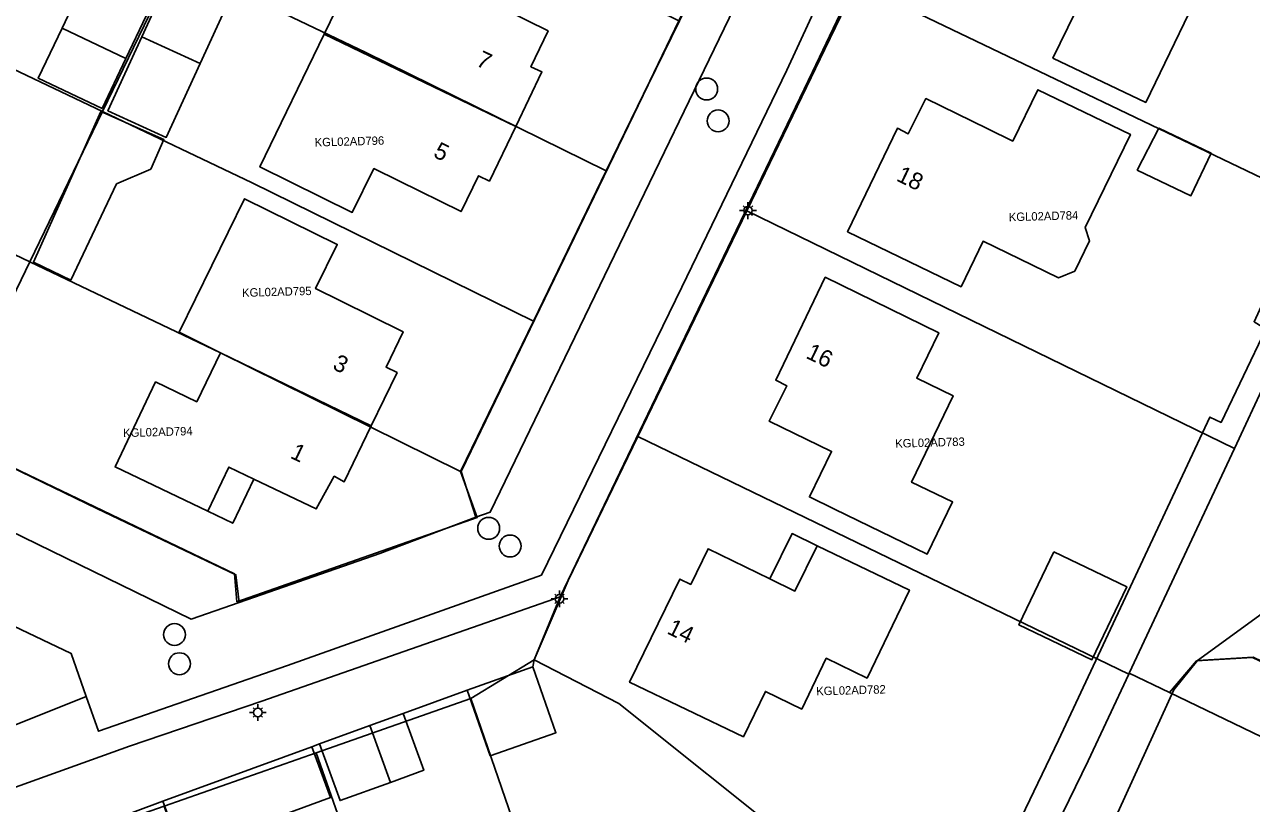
# Model space of a CAD drawing. Extents: x 124901 to 125496, y 515369 to 515789.
# Drawn here: x 125375.1 to 125447.9, y 515642.6 to 515688.8 of the extents above; entities that cross this region are included whole.
import ezdxf

# ---------------------------------------------------------------- set-up
doc = ezdxf.new("R2010")
doc.units = 0
for name, color, linetype in [('Gebouw', 7, 'Continuous'), ('Lichtmast', 7, 'Continuous'), ('Luifel', 7, 'Continuous'), ('Onbegroeid terrein', 7, 'Continuous'), ('Parkeren', 7, 'Continuous'), ('Perceelnummers', 7, 'Continuous'), ('Perceelsgrenzen', 7, 'Continuous'), ('Putten', 7, 'Continuous'), ('Scheiding', 7, 'Continuous'), ('Teksten', 7, 'Continuous'), ('Vegetatie', 7, 'Continuous'), ('Voetpad', 7, 'Continuous'), ('Water', 7, 'Continuous'), ('Wegen lokale weg', 7, 'Continuous')]:
    doc.layers.add(name, color=color, linetype=linetype)

msp = doc.modelspace()

# ---------------------------------------------------------------- linework, layer by layer
at = {"layer": 'Gebouw'}
for points in [[(125433.312, 515694.13), (125432.28, 515692), (125435.972, 515690.217), (125437.458, 515689.5), (125436.149, 515686.79), (125441.65, 515684.17), (125445.627, 515692.406), (125441.046, 515694.619), (125442.35, 515697.32), (125435.61, 515700.54), (125432.65, 515694.45)], [(125405.175, 515686.283), (125406.19, 515688.41), (125402.491, 515690.233), (125401.011, 515690.963), (125402.299, 515693.575), (125396.814, 515696.279), (125392.911, 515688.22), (125404.274, 515682.742), (125405.83, 515685.97)], [(125381.148, 515686.776), (125377.355, 515688.574), (125375.945, 515685.598), (125379.738, 515683.8)], [(125402.712, 515679.503), (125404.274, 515682.742), (125392.911, 515688.22), (125389.097, 515680.344), (125394.572, 515677.638), (125395.861, 515680.245), (125397.34, 515679.514), (125401.03, 515677.69), (125402.056, 515679.819)], [(125380.081, 515683.67), (125383.542, 515682.087), (125385.548, 515686.474), (125382.086, 515688.057)], [(125423.96, 515676.5), (125430.7, 515673.238), (125432.007, 515675.938), (125434.167, 515674.892), (125436.485, 515673.77), (125437.445, 515674.165), (125438.313, 515675.96), (125438.06, 515676.74), (125440.74, 515682.27), (125435.25, 515684.92), (125433.766, 515681.876), (125432.283, 515682.599), (125428.61, 515684.39), (125427.564, 515682.307), (125426.92, 515682.63)], [(125393.684, 515675.747), (125388.182, 515678.455), (125384.313, 515670.544), (125386.751, 515669.309), (125395.701, 515664.985), (125397.23, 515668.15), (125396.58, 515668.461), (125397.59, 515670.57), (125393.875, 515672.398), (125392.395, 515673.127)], [(125428.07, 515667.805), (125429.37, 515670.51), (125422.64, 515673.8), (125419.7, 515667.69), (125420.355, 515667.368), (125419.32, 515665.26), (125423.012, 515663.468), (125421.7, 515660.768), (125423.184, 515660.047), (125428.684, 515657.376), (125430.19, 515660.48), (125427.764, 515661.646), (125430.226, 515666.768)], [(125392.44, 515660.06), (125393.503, 515661.997), (125394.1, 515661.67), (125395.701, 515664.985), (125386.751, 515669.309), (125385.349, 515666.414), (125382.907, 515667.596), (125380.5, 515662.55), (125385.996, 515659.928), (125387.25, 515662.546), (125388.738, 515661.833)], [(125419.09, 515649.238), (125421.24, 515648.19), (125422.699, 515651.203), (125425.12, 515650.03), (125427.628, 515655.247), (125422.15, 515657.88), (125420.841, 515655.189), (125419.357, 515655.911), (125415.684, 515657.698), (125414.655, 515655.582), (125414, 515655.9), (125411.03, 515649.78), (125417.78, 515646.55)], [(125392.627, 515646.124), (125393.848, 515642.761), (125396.839, 515643.846), (125395.619, 515647.21)]]:
    msp.add_lwpolyline(points, close=True, dxfattribs=at)
at = {"layer": 'Lichtmast'}
for p, q in [((125417.837, 515677.963), (125417.767, 515678.034)), ((125418.049, 515678.051), (125418.049, 515678.251)), ((125418.261, 515677.963), (125418.332, 515678.035)), ((125417.749, 515677.752), (125417.549, 515677.751)), ((125417.837, 515677.539), (125417.765, 515677.468)), ((125418.049, 515677.451), (125418.049, 515677.251)), ((125418.261, 515677.539), (125418.331, 515677.468)), ((125418.349, 515677.751), (125418.549, 515677.751)), ((125406.57, 515654.73), (125406.37, 515654.729)), ((125406.658, 515654.941), (125406.588, 515655.012)), ((125406.87, 515655.029), (125406.87, 515655.229)), ((125407.082, 515654.941), (125407.153, 515655.013)), ((125407.17, 515654.729), (125407.37, 515654.729)), ((125406.658, 515654.517), (125406.586, 515654.446)), ((125406.87, 515654.429), (125406.87, 515654.229)), ((125407.082, 515654.517), (125407.152, 515654.446)), ((125388.759, 515648.201), (125388.689, 515648.272)), ((125388.971, 515648.289), (125388.971, 515648.489)), ((125389.183, 515648.201), (125389.254, 515648.273)), ((125388.671, 515647.99), (125388.471, 515647.989)), ((125388.759, 515647.777), (125388.687, 515647.706)), ((125388.971, 515647.689), (125388.971, 515647.489)), ((125389.183, 515647.777), (125389.253, 515647.706)), ((125389.271, 515647.989), (125389.471, 515647.989))]:
    msp.add_line(p, q, dxfattribs=at)
for centre in [(125418.049, 515677.751), (125406.87, 515654.729), (125388.971, 515647.989)]:
    msp.add_circle(centre, 0.25, dxfattribs=at)
at = {"layer": 'Luifel'}
for points in [[(125382.086, 515688.057), (125385.548, 515686.474), (125387.563, 515690.88), (125384.101, 515692.462)], [(125381.148, 515686.776), (125382.347, 515689.306), (125378.554, 515691.104), (125377.355, 515688.574)], [(125380.581, 515679.332), (125382.615, 515680.203), (125383.401, 515681.963), (125379.663, 515683.632), (125375.665, 515674.683), (125377.869, 515673.634)], [(125442.422, 515682.631), (125441.152, 515680.149), (125444.338, 515678.632), (125445.536, 515681.147)], [(125388.738, 515661.833), (125387.25, 515662.546), (125385.996, 515659.928), (125387.484, 515659.215)], [(125420.841, 515655.189), (125422.15, 515657.88), (125420.666, 515658.602), (125419.357, 515655.911)], [(125436.2, 515657.509), (125434.132, 515653.185), (125438.456, 515651.117), (125440.524, 515655.441)], [(125401.387, 515649.315), (125402.76, 515645.414), (125406.661, 515646.787), (125405.288, 515650.687)], [(125397.596, 515647.927), (125395.619, 515647.21), (125396.839, 515643.846), (125398.817, 515644.564)], [(125392.17, 515645.96), (125383.332, 515642.723), (125384.436, 515639.707), (125393.275, 515642.944)]]:
    msp.add_lwpolyline(points, close=True, dxfattribs=at)
at = {"layer": 'Onbegroeid terrein'}
for points in [[(125387.675, 515656.161), (125387.857, 515654.507), (125396.207, 515657.408), (125401.906, 515659.565), (125401.03, 515662.274), (125412.127, 515685.205), (125422.352, 515706.097), (125424.481, 515710.447), (125424.391, 515710.491), (125423.853, 515710.375), (125408.558, 515717.624), (125373.683, 515734.37), (125372.5, 515731.951), (125364.983, 515716.105), (125345.743, 515676.245), (125361.449, 515668.777), (125379.413, 515660.079)], [(125432.28, 515692), (125433.312, 515694.13), (125432.65, 515694.45), (125435.61, 515700.54), (125442.35, 515697.32), (125441.046, 515694.619), (125445.627, 515692.406), (125441.65, 515684.17), (125436.149, 515686.79), (125437.458, 515689.5), (125435.972, 515690.217)], [(125404.274, 515682.742), (125402.712, 515679.503), (125402.056, 515679.819), (125401.03, 515677.69), (125397.34, 515679.514), (125395.861, 515680.245), (125394.572, 515677.638), (125389.097, 515680.344), (125392.911, 515688.22), (125396.814, 515696.279), (125402.299, 515693.575), (125401.011, 515690.963), (125402.491, 515690.233), (125406.19, 515688.41), (125405.175, 515686.283), (125405.83, 515685.97)], [(125377.355, 515688.574), (125381.148, 515686.776), (125379.738, 515683.8), (125375.945, 515685.598)], [(125385.548, 515686.474), (125383.542, 515682.087), (125380.081, 515683.67), (125382.086, 515688.057)], [(125430.7, 515673.238), (125423.96, 515676.5), (125426.92, 515682.63), (125427.564, 515682.307), (125428.61, 515684.39), (125432.283, 515682.599), (125433.766, 515681.876), (125435.25, 515684.92), (125440.74, 515682.27), (125438.06, 515676.74), (125438.313, 515675.96), (125437.445, 515674.165), (125436.485, 515673.77), (125434.167, 515674.892), (125432.007, 515675.938)], [(125393.503, 515661.997), (125392.44, 515660.06), (125388.738, 515661.833), (125387.25, 515662.546), (125385.996, 515659.928), (125380.5, 515662.55), (125382.907, 515667.596), (125385.349, 515666.414), (125386.751, 515669.309), (125384.313, 515670.544), (125388.182, 515678.455), (125393.684, 515675.747), (125392.395, 515673.127), (125393.875, 515672.398), (125397.59, 515670.57), (125396.58, 515668.461), (125397.23, 515668.15), (125395.701, 515664.985), (125394.1, 515661.67)], [(125429.37, 515670.51), (125428.07, 515667.805), (125430.226, 515666.768), (125427.764, 515661.646), (125430.19, 515660.48), (125428.684, 515657.376), (125423.184, 515660.047), (125421.7, 515660.768), (125423.012, 515663.468), (125419.32, 515665.26), (125420.355, 515667.368), (125419.7, 515667.69), (125422.64, 515673.8)], [(125421.24, 515648.19), (125419.09, 515649.238), (125417.78, 515646.55), (125411.03, 515649.78), (125414, 515655.9), (125414.655, 515655.582), (125415.684, 515657.698), (125419.357, 515655.911), (125420.841, 515655.189), (125422.15, 515657.88), (125427.628, 515655.247), (125425.12, 515650.03), (125422.699, 515651.203)]]:
    msp.add_lwpolyline(points, close=True, dxfattribs=at)
for points in [[(125429.798, 515702.583), (125421.887, 515685.97), (125412.818, 515667.163), (125406.911, 515654.851), (125405.36, 515651.11), (125405.288, 515650.687), (125401.387, 515649.315), (125397.596, 515647.927), (125395.619, 515647.21), (125396.839, 515643.846), (125393.848, 515642.761), (125392.627, 515646.124), (125392.17, 515645.96), (125383.332, 515642.723), (125378.729, 515641.005), (125374.409, 515639.418)], [(125490.925, 515630.677), (125448.027, 515651.268), (125444.728, 515651.073), (125443.321, 515649.329), (125433.556, 515627.939), (125431.85, 515627.386), (125429.766, 515628.208), (125428.663, 515630.094), (125436.481, 515646.34), (125445.451, 515665.509), (125446.119, 515665.186), (125448.787, 515670.727), (125448.083, 515671.163), (125452.441, 515680.669), (125457.131, 515690.833)]]:
    msp.add_lwpolyline(points, dxfattribs=at)
at = {"layer": 'Parkeren'}
msp.add_lwpolyline([(125424.616, 515705.029), (125422.352, 515706.097), (125412.127, 515685.205), (125401.03, 515662.274), (125401.906, 515659.565), (125402.757, 515659.867)], close=True, dxfattribs=at)
at = {"layer": 'Perceelsgrenzen'}
for points in [[(125345.632, 515676.323), (125350.605, 515686.696), (125354.889, 515695.633), (125359.171, 515704.565), (125363.512, 515713.469), (125367.85, 515722.367), (125374.626, 515736.264), (125398.05, 515725.06), (125399.454, 515724.383), (125423.37, 515712.85), (125423.634, 515712.729), (125425.072, 515712.068), (125418.239, 515697.902), (125413.944, 515688.996), (125412.226, 515685.435), (125409.64, 515680.099), (125405.324, 515671.192), (125401, 515662.27), (125401.99, 515659.56), (125387.73, 515654.56), (125387.592, 515656.202), (125370.466, 515664.415)], [(125453.316, 515677.409), (125424.5, 515691.221), (125432.811, 515708.356), (125432.874, 515708.485), (125461.248, 515694.727)], [(125354.889, 515695.633), (125359.171, 515704.565), (125372.598, 515698.005), (125384.059, 515692.535), (125379.751, 515683.623), (125370.719, 515687.915)], [(125409.64, 515680.099), (125395.383, 515687.131), (125384.059, 515692.535), (125388.371, 515701.456), (125397.272, 515697.224), (125413.944, 515688.996), (125412.226, 515685.435)], [(125350.605, 515686.696), (125354.889, 515695.633), (125370.719, 515687.915), (125379.751, 515683.623), (125375.444, 515674.713), (125363.983, 515680.184)], [(125405.324, 515671.192), (125388.639, 515679.4), (125379.751, 515683.623), (125384.059, 515692.535), (125395.383, 515687.131), (125409.64, 515680.099)], [(125417.983, 515677.745), (125422.606, 515687.317), (125424.5, 515691.221), (125453.316, 515677.409), (125452.553, 515675.743), (125446.912, 515663.647)], [(125350.605, 515686.696), (125363.983, 515680.184), (125375.444, 515674.713), (125370.466, 515664.415), (125345.632, 515676.323)], [(125401, 515662.27), (125386.754, 515669.315), (125375.444, 515674.713), (125379.751, 515683.623), (125388.639, 515679.4), (125405.324, 515671.192)], [(125440.672, 515650.329), (125440.645, 515650.271), (125411.516, 515664.357), (125417.983, 515677.745), (125446.912, 515663.647)], [(125370.466, 515664.415), (125375.444, 515674.713), (125386.754, 515669.315), (125401, 515662.27), (125401.99, 515659.56), (125387.73, 515654.56), (125387.592, 515656.202)], [(125405.36, 515651.11), (125407.38, 515655.81), (125411.516, 515664.357), (125440.645, 515650.271), (125438.238, 515645.132), (125432.962, 515634.284), (125420.94, 515640.11), (125410.39, 515648.52)], [(125410.753, 515622.315), (125401.6, 515648.81), (125405.36, 515651.11), (125410.39, 515648.52), (125420.94, 515640.11), (125432.962, 515634.284), (125430.488, 515629.198)], [(125443.053, 515649.181), (125444.658, 515651.051), (125447.978, 515651.259), (125460.02, 515645.53), (125463.963, 515643.642), (125462.19, 515639.955)], [(125458.523, 515632.331), (125454.483, 515623.931), (125454.428, 515623.816), (125453.982, 515624.032), (125448.8, 515613.204), (125432.377, 515621.151), (125427.879, 515623.328), (125430.488, 515629.198), (125432.962, 515634.284), (125438.238, 515645.132), (125440.645, 515650.271), (125440.672, 515650.329), (125443.053, 515649.181), (125462.19, 515639.955), (125462.144, 515639.859), (125461.924, 515639.69), (125461.215, 515638.361), (125459.902, 515635.812), (125458.642, 515633.35)], [(125401.726, 515619.167), (125392.439, 515645.595), (125401.6, 515648.81), (125410.753, 515622.315)], [(125392.524, 515615.957), (125383.42, 515642.43), (125392.439, 515645.595), (125401.726, 515619.167)]]:
    msp.add_lwpolyline(points, close=True, dxfattribs=at)
for points in [[(125461.248, 515694.727), (125453.316, 515677.409), (125452.553, 515675.743), (125446.912, 515663.647), (125440.672, 515650.329), (125443.053, 515649.181), (125444.658, 515651.051), (125447.978, 515651.259), (125460.02, 515645.53), (125463.963, 515643.642), (125481.177, 515635.398), (125481.222, 515635.377), (125481.552, 515635.219), (125490.925, 515630.741)], [(125374.35, 515639.28), (125383.42, 515642.43), (125392.439, 515645.595), (125401.6, 515648.81), (125405.36, 515651.11), (125407.38, 515655.81), (125411.516, 515664.357), (125417.983, 515677.745), (125422.606, 515687.317), (125424.5, 515691.221)]]:
    msp.add_lwpolyline(points, dxfattribs=at)
at = {"layer": 'Putten'}
for centre in [(125415.6, 515684.96), (125416.28, 515683.07), (125402.67, 515658.91), (125403.94, 515657.86), (125384.03, 515652.61), (125384.32, 515650.88)]:
    msp.add_circle(centre, 0.65, dxfattribs=at)
at = {"layer": 'Scheiding'}
msp.add_lwpolyline([(125361.449, 515668.777), (125379.413, 515660.079)], dxfattribs=at)
at = {"layer": 'Vegetatie'}
for points in [[(125387.857, 515654.507), (125387.675, 515656.161), (125379.413, 515660.079), (125361.449, 515668.777), (125345.743, 515676.245), (125344.287, 515673.229), (125344.617, 515672.981), (125344.963, 515672.755), (125345.959, 515672.271), (125361.779, 515664.844), (125385.018, 515653.521)], [(125368.071, 515656.163), (125365.82, 515651.552), (125374.603, 515647.262), (125378.796, 515648.945), (125377.898, 515651.479), (125370.197, 515655.148)]]:
    msp.add_lwpolyline(points, close=True, dxfattribs=at)
msp.add_lwpolyline([(125374.409, 515639.418), (125378.729, 515641.005), (125383.332, 515642.723), (125392.17, 515645.96), (125392.627, 515646.124), (125395.619, 515647.21), (125397.596, 515647.927), (125401.387, 515649.315), (125405.288, 515650.687), (125405.36, 515651.11), (125406.911, 515654.851), (125389.202, 515648.653), (125381.355, 515645.99), (125372.6, 515642.854)], dxfattribs=at)
at = {"layer": 'Voetpad'}
msp.add_lwpolyline([(125372.6, 515642.854), (125381.355, 515645.99), (125389.202, 515648.653), (125406.911, 515654.851), (125412.818, 515667.163), (125421.887, 515685.97), (125429.798, 515702.583), (125430.732, 515704.484), (125430.629, 515704.536), (125429.368, 515705.152), (125429.265, 515705.202), (125428.315, 515703.282), (125420.361, 515686.071), (125414.125, 515673.202), (125405.801, 515656.14), (125390.738, 515650.782), (125379.528, 515646.88), (125378.796, 515648.945), (125374.603, 515647.262)], dxfattribs=at)
at = {"layer": 'Water'}
for points in [[(125457.131, 515690.833), (125452.441, 515680.669), (125448.083, 515671.163), (125448.787, 515670.727), (125446.119, 515665.186), (125445.451, 515665.509), (125436.481, 515646.34), (125428.663, 515630.094), (125429.766, 515628.208), (125431.85, 515627.386), (125433.556, 515627.939), (125443.321, 515649.329), (125444.728, 515651.073), (125454.573, 515658.231), (125461.167, 515672.009), (125466.419, 515682.908), (125469.241, 515688.71), (125472.559, 515695.531)], [(125484.458, 515640.311), (125479.957, 515642.488), (125478.294, 515643.292), (125478.266, 515643.281), (125477.672, 515643.566), (125456.22, 515653.859), (125454.714, 515655.957), (125454.573, 515658.231), (125444.728, 515651.073), (125448.027, 515651.268), (125490.925, 515630.677)]]:
    msp.add_lwpolyline(points, dxfattribs=at)
at = {"layer": 'Wegen lokale weg'}
for points in [[(125425.14, 515704.782), (125424.616, 515705.029), (125402.757, 515659.867), (125401.906, 515659.565), (125396.207, 515657.408), (125387.857, 515654.507), (125385.018, 515653.521), (125361.779, 515664.844), (125345.959, 515672.271), (125344.963, 515672.755), (125344.617, 515672.981), (125344.287, 515673.229)], [(125370.197, 515655.148), (125377.898, 515651.479), (125378.796, 515648.945), (125379.528, 515646.88), (125390.738, 515650.782), (125405.801, 515656.14), (125414.125, 515673.202), (125420.361, 515686.071), (125428.315, 515703.282), (125428.111, 515703.379), (125425.14, 515704.782)]]:
    msp.add_lwpolyline(points, dxfattribs=at)

# ---------------------------------------------------------------- texts
at = {"layer": 'Perceelnummers'}
for s, rotation, p in [('KGL02AD796', 1.63445, (125392.35, 515681.545)), ('KGL02AD784', 1.63493, (125433.534, 515677.115)), ('KGL02AD795', 1.6344, (125388.043, 515672.628)), ('KGL02AD794', 1.63432, (125380.985, 515664.318)), ('KGL02AD783', 1.63485, (125426.796, 515663.689)), ('KGL02AD782', 1.6348, (125422.109, 515649.002))]:
    msp.add_text(s, height=0.5, rotation=rotation, dxfattribs=at).set_placement(p)
at = {"layer": 'Teksten'}
for s, rotation, p in [('7', 334.3, (125401.863, 515686.38)), ('5', 333.7, (125399.322, 515680.968)), ('18', 334.2, (125426.798, 515679.548)), ('16', 334.3, (125421.432, 515669.033)), ('3', 334.2, (125393.349, 515668.381)), ('1', 334.4, (125390.838, 515663.109)), ('14', 334.1, (125413.189, 515652.696))]:
    msp.add_text(s, height=1, rotation=rotation, dxfattribs=at).set_placement(p)

doc.saveas('drawing.dxf')
